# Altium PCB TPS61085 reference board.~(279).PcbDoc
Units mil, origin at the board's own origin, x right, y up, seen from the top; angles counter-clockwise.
Board outline 2400 x 2000 mil, 2 copper layers (Top Layer, Bottom Layer), stack 62 mil thick; 54 components, 22 nets, 101 pads, 29 vias.
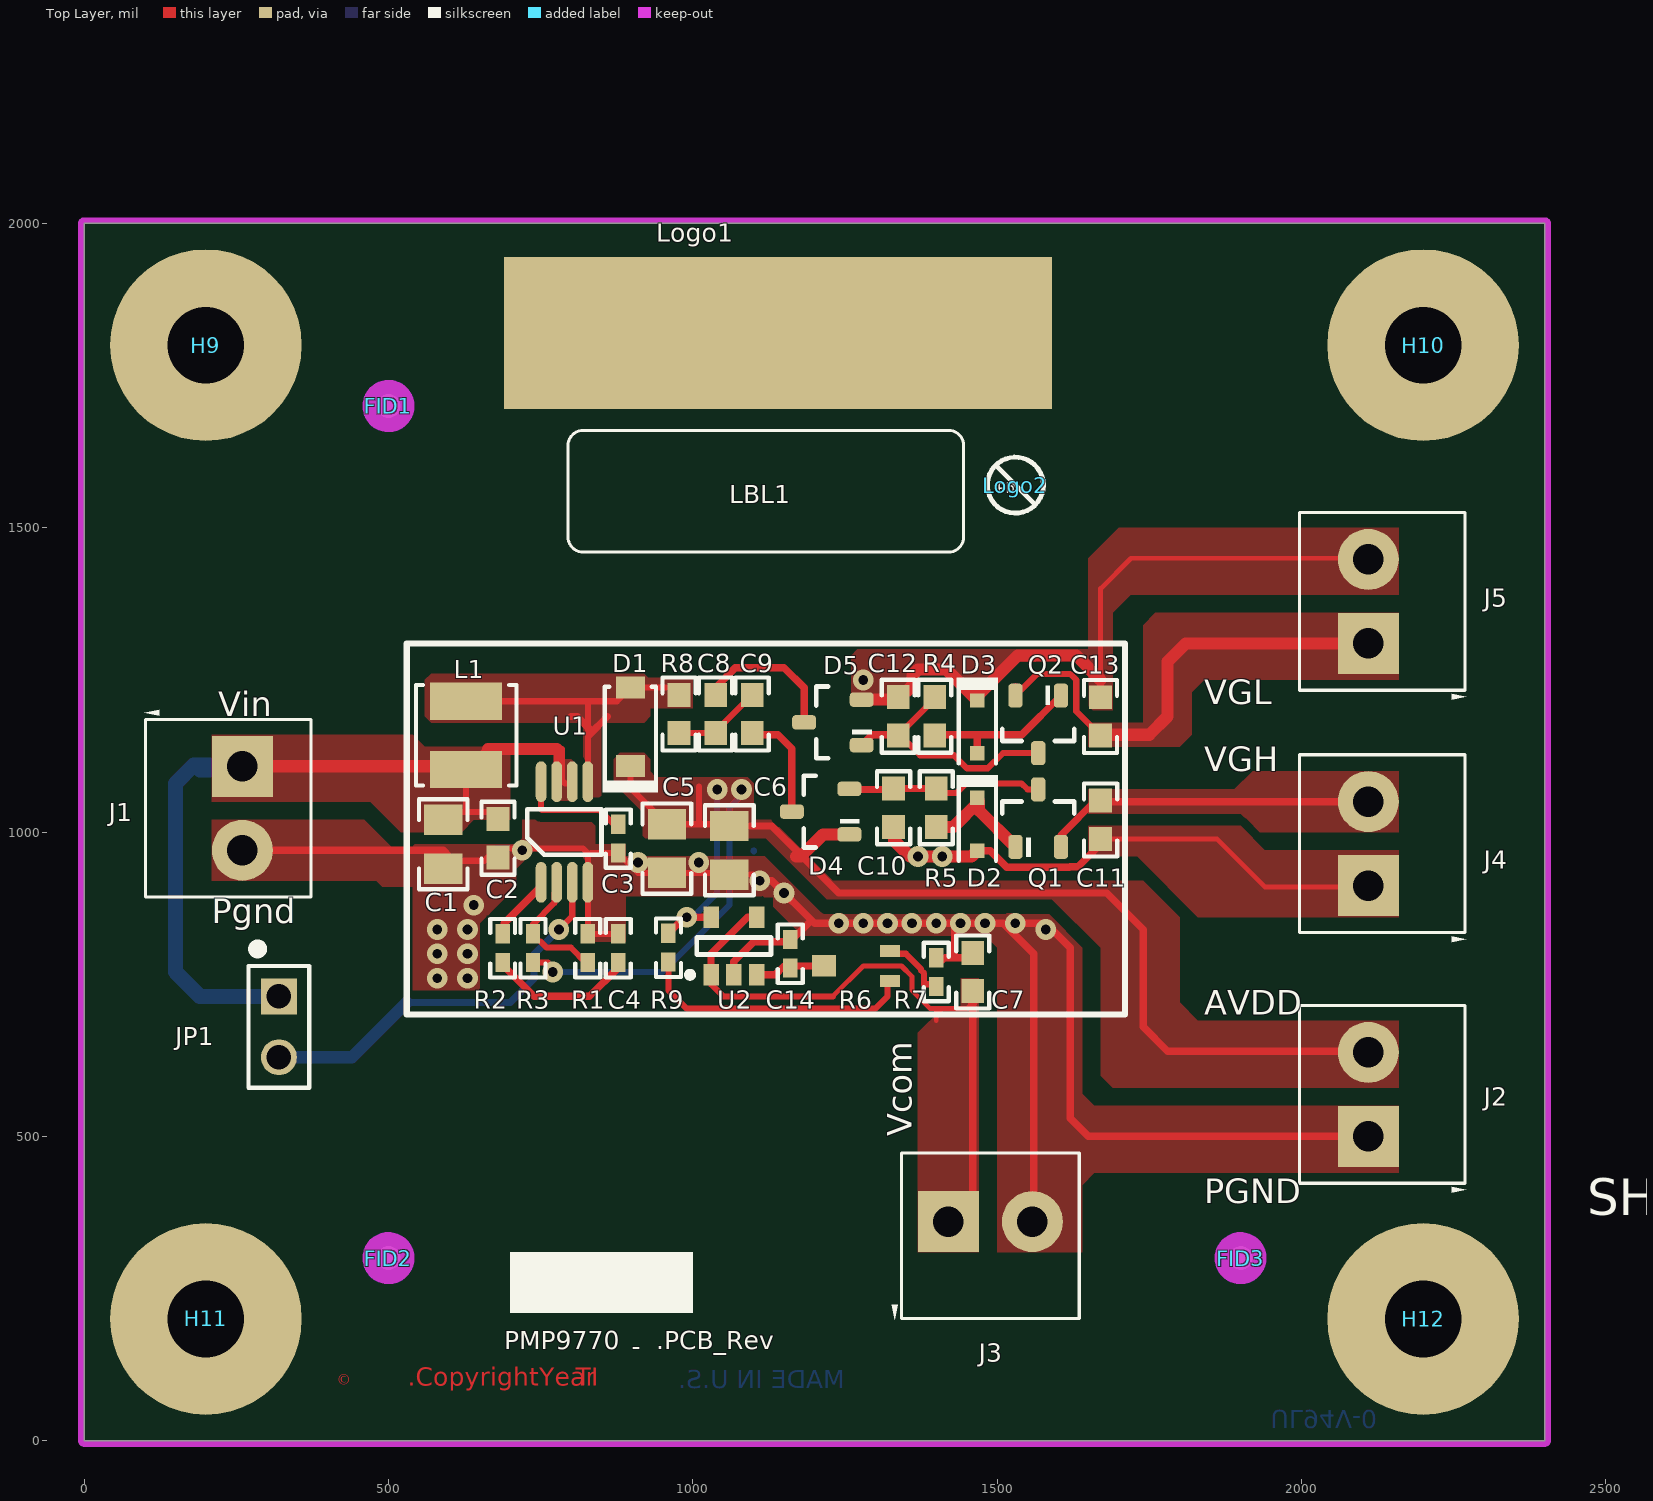
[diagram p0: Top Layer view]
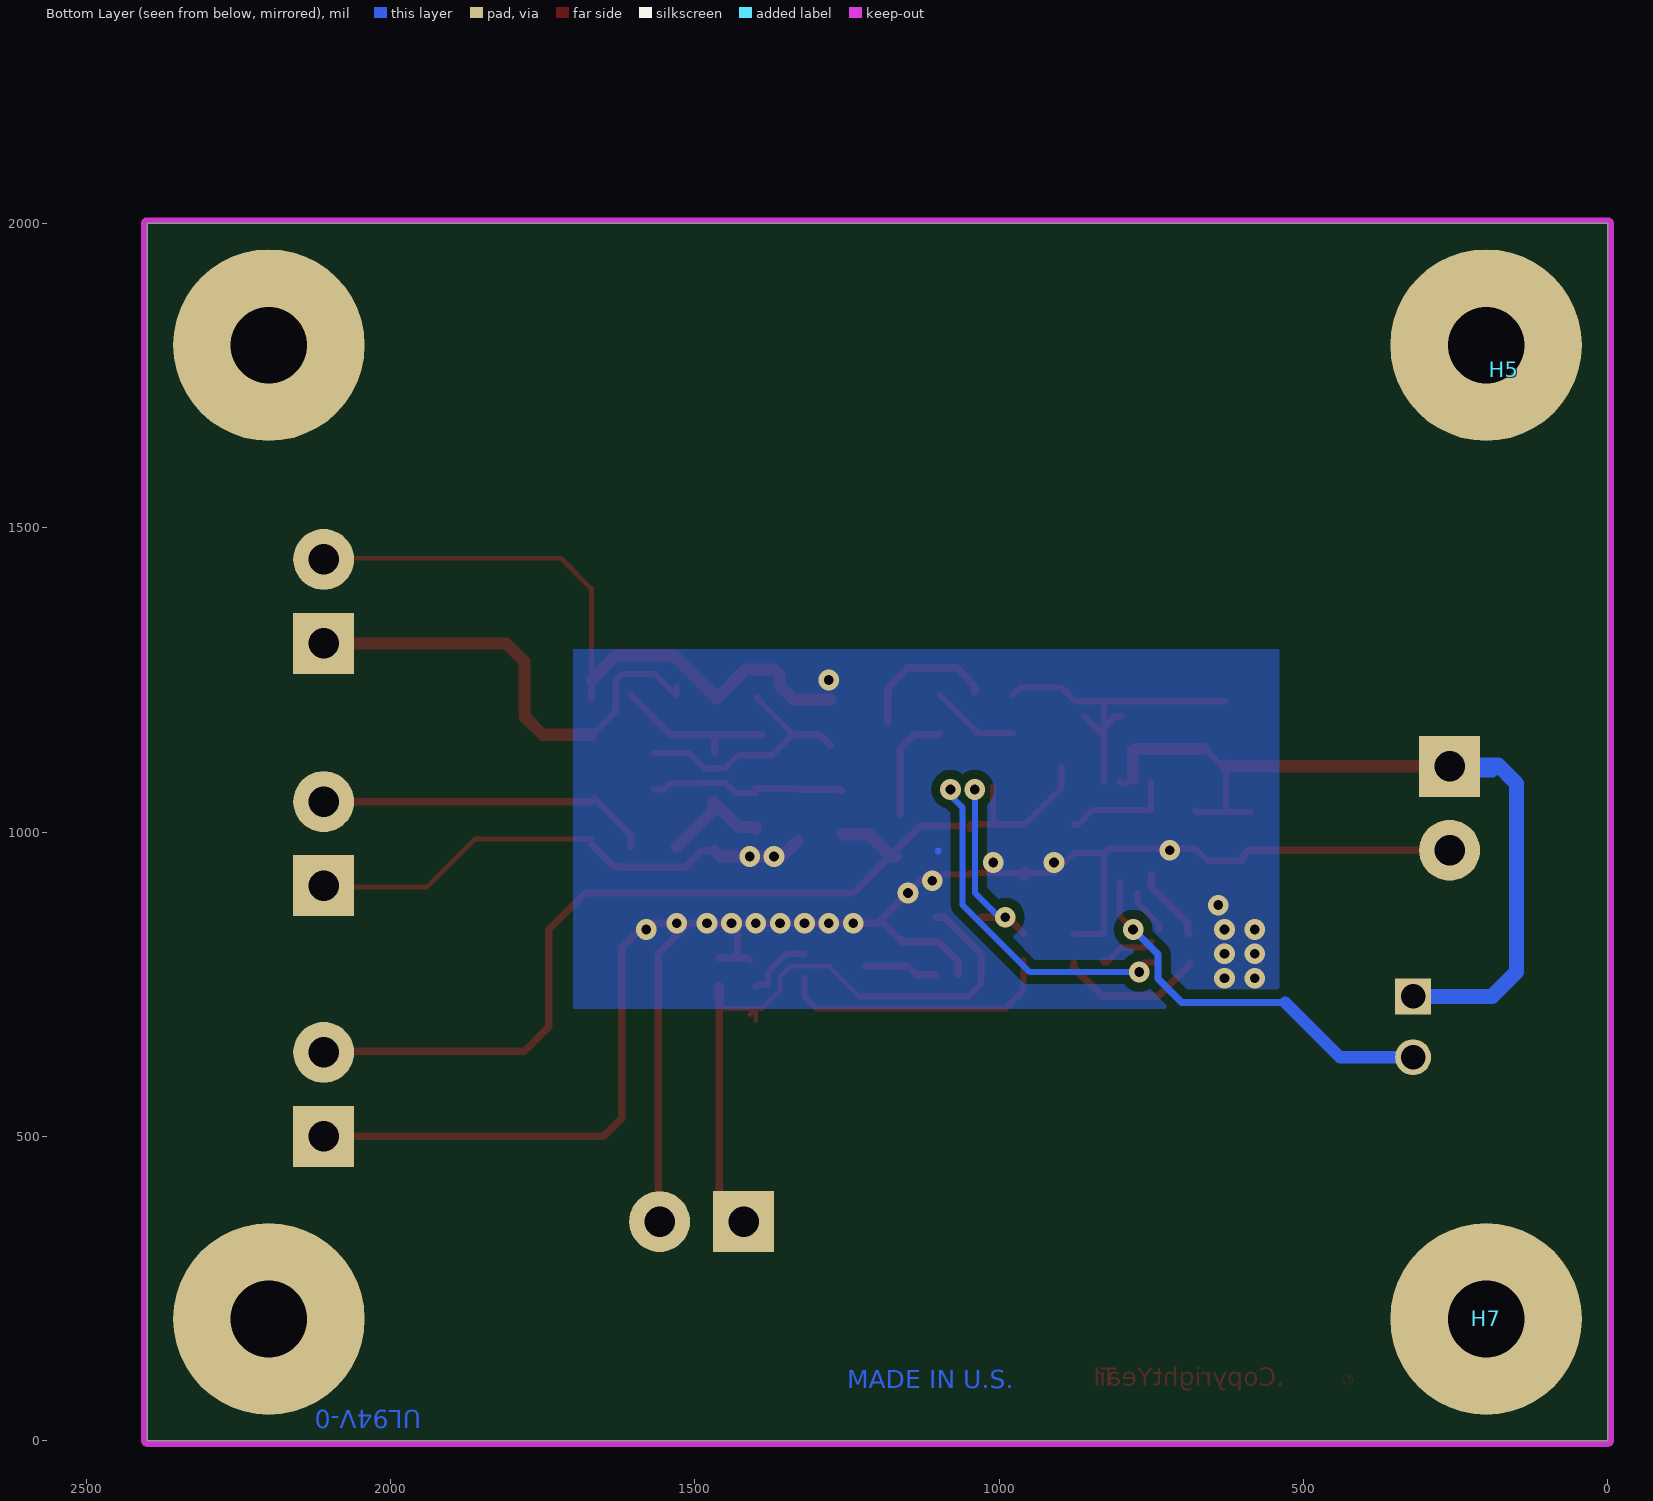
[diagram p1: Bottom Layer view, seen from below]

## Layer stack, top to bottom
Top Solder: solder mask 0.4, Solder Resist, Dk 3.5
Top Layer: signal copper 1.4
Dielectric1: core 59.2, FR-4, Dk 4.8
Bottom Layer: signal copper 1.4
Bottom Solder: solder mask 0.4, Solder Resist, Dk 3.5

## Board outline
0,0 2400,0 2400,2000 0,2000

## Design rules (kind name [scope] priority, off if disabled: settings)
AcuteAngle [All] p1: minimum=4.50000000000000E+0001 checktracksonly=FALSE
AssemblyTestPointUsage [All] p1: valid=2
Clearance Clearance_2 [InNamedPolygon('Top Layer-No Net 4')] p1: gap=10
Clearance Clearance_1 [InNamedPolygon('Top Layer-No Net 4')] p2: gap=10
Clearance Clearance_Keepouts [((IsTrack Or IsArc) And Not InPoly) And IsFree and IsKeepOut vs ((IsTrack Or IsArc) And Not InPoly) And IsFree and IsKeepOut] p3: gap=8
Clearance Clearance_BoardEdge_MountingHoles [OnCopper and InComponentClass('Mounting Holes') vs IsKeepOut] p4: gap=40
Clearance Clearance_BoardEdge_Poly [OnCopper and InPoly vs IsKeepOut] p5: gap=25
Clearance Clearance_BoardEdge [OnCopper and Not InComponentClass('Logo') and not InComponentClass('FiducialMark') and not InRegion(1000,500,4000,800) and Not IsKeepout vs IsKeepOut] p6: gap=75
Clearance Clearance_Poly [InPolygon] p7: gap=15
Clearance [All] p8: gap=7.87
ComponentClearance ComponentClearance_MountingHoles_FiducialMarks [InComponentClass('Mounting Holes') vs InComponentClass('FiducialMark')] p1: gap=10 collisioncheckmode=3 verticalgap=10 showdistances=FALSE
ComponentClearance ComponentClearance_Shunt [InComponentClass('Header') vs InComponentClass('Shunt')] p2: gap=0 collisioncheckmode=3 verticalgap=0 showdistances=FALSE
ComponentClearance ComponentClearance_Logo [InComponentClass('Logo')] p3: gap=10 collisioncheckmode=3 verticalgap=10 showdistances=FALSE
ComponentClearance ComponentClearance_ScrewToNut [(HasFootprint('NY PMS 440 0025 PH')) vs (HasFootprint('Keystone_1902C'))] p4: gap=5 collisioncheckmode=3 verticalgap=10 showdistances=FALSE
ComponentClearance ComponentClearance_MountingHoles [InComponentClass('Mounting Holes')] p5: gap=250 collisioncheckmode=3 verticalgap=100000 showdistances=FALSE
ComponentClearance ComponentClearance_SmallPassives [HasFootprint('0201*') or HasFootprint('0402*') or HasFootprint('0508') or HasFootprint('0603*') or HasFootprint('0612') or HasFootprint('0805*') or HasFootprint('0815*') or HasFootprint('0830*') or HasFootprint('1206*') or HasFootprint('1210*') or HasFootprint('1808*') or HasFootprint('1812*') or HasFootprint('1825*') or HasFootprint('2010*') or HasFootprint('2220*') or HasFootprint('2225*') or HasFootprint('2512*') or HasFootprint('2728*') or HasFootprint('3518*') vs HasFootprint('0201*') or HasFootprint('0402*') or HasFootprint('0508') or HasFootprint('0603*') or HasFootprint('0612') or HasFootprint('0805*') or HasFootprint('0815*') or HasFootprint('0830*') or HasFootprint('1206*') or HasFootprint('1210*') or HasFootprint('1808*') or HasFootprint('1812*') or HasFootprint('1825*') or HasFootprint('2010*') or HasFootprint('2220*') or HasFootprint('2225*') or HasFootprint('2512*') or HasFootprint('2728*') or HasFootprint('3518*')] p6: gap=20 collisioncheckmode=3 verticalgap=10 showdistances=FALSE
ComponentClearance ComponentClearance_THtoSMT [IsThruComponent vs IsSMTComponent] p7: gap=100 collisioncheckmode=3 verticalgap=30 showdistances=FALSE
ComponentClearance ComponentClearance_THtoTH [IsThruComponent vs IsThruComponent] p8: gap=118.11 collisioncheckmode=3 verticalgap=30 showdistances=FALSE
ComponentClearance [All] p9: gap=10 collisioncheckmode=3 verticalgap=10 showdistances=FALSE
DiffPairsRouting [All] p1: maxlimit=100 minlimit=10 mostfreqgap=10 toplayer_minwidth=15 toplayer_maxwidth=15 toplayer_prefwidth=15 bottomlayer_minwidth=15 bottomlayer_maxwidth=15 bottomlayer_prefwidth=15 maxuncoupledlength=1000
FabricationTestPointUsage TestPointUsage [All] p1: valid=2 allowmultiple=FALSE
FabricationTestpoint Testpoint [All] p1: side=3 testpointundercomponent=TRUE minsize=40 maxsize=100 preferedsize=60 minholesize=0 maxholesize=40 preferedholesize=32 testpointgrid=1 allowsidetop=TRUE allowsidebottom=TRUE usegrid=TRUE gridtolerance=0.01
FanoutControl Fanout_LCC [IsLCC] p1: bgadir=Out bgaviamode=Centered fanoutstyle=Auto fanoutdirection=Alternating viagrid=1 // Fanout_LCC (Default Rule)
FanoutControl Fanout_BGA [IsBGA] p2: bgadir=Out bgaviamode=Centered fanoutstyle=Auto fanoutdirection=Alternating viagrid=1 // Fanout_BGA (Default Rule)
FanoutControl Fanout_Default [All] p4: bgadir=Out bgaviamode=Centered fanoutstyle=Auto fanoutdirection=Alternating viagrid=1 // Fanout_Default (Default Rule)
FanoutControl Fanout_Small [(CompPinCount < 5)] p5: bgadir=Out bgaviamode=Centered fanoutstyle=Auto fanoutdirection=OutThenIn viagrid=1 // Fanout_Small (Default Rule)
HoleSize [All] p1: absolutevalues=TRUE maxlimit=251 minlimit=8 maxpercent=80.000 minpercent=20.000
MinimumAnnularRing MinimumAnnularRing_ThermalPadVias [IsVia and InAnyComponent] p1: minimumring=5.91
MinimumAnnularRing [All] p2: minimumring=9
MinimumSolderMaskSliver MinimumSolderMaskSliver_Logo [InComponentClass('Logo') vs InComponentClass('Logo')] p1: minsoldermaskwidth=0.7
MinimumSolderMaskSliver [All] p2: minsoldermaskwidth=3.94
PlaneConnect [All] p1: planeconnectstyle=Direct reliefexpansion=10 reliefentries=4 reliefconductorwidth=10 reliefairgap=10
PolygonConnect PolygonConnect_9 [All vs IsNamedPolygon('Top Layer-No Net 9')] p1: connectstyle=Direct reliefconductorwidth=10 reliefentries=4 polygonreliefangle="90 Angle" airgapwidth=10
PolygonConnect PolygonConnect_8 [All vs IsNamedPolygon('Top Layer-No Net 9')] p2: connectstyle=Direct reliefconductorwidth=10 reliefentries=4 polygonreliefangle="90 Angle" airgapwidth=10
PolygonConnect PolygonConnect_7 [All vs IsNamedPolygon('Top Layer-No Net 9')] p3: connectstyle=Direct reliefconductorwidth=10 reliefentries=4 polygonreliefangle="90 Angle" airgapwidth=10
PolygonConnect PolygonConnect_6 [All vs IsNamedPolygon('Top Layer-No Net 4')] p4: connectstyle=Direct reliefconductorwidth=10 reliefentries=4 polygonreliefangle="90 Angle" airgapwidth=10
PolygonConnect PolygonConnect_5 [All vs IsNamedPolygon('Top Layer-No Net 3') Or  IsNamedPolygon('Top Layer-No Net')] p5: connectstyle=Direct reliefconductorwidth=10 reliefentries=4 polygonreliefangle="90 Angle" airgapwidth=10
PolygonConnect PolygonConnect_4 [All vs IsNamedPolygon('Top Layer-No Net')] p6: connectstyle=Direct reliefconductorwidth=10 reliefentries=4 polygonreliefangle="90 Angle" airgapwidth=10
PolygonConnect PolygonConnect_3 [All vs IsNamedPolygon('Top Layer-No Net 2') Or  IsNamedPolygon('Top Layer-No Net')] p7: connectstyle=Direct reliefconductorwidth=10 reliefentries=4 polygonreliefangle="90 Angle" airgapwidth=10
PolygonConnect PolygonConnect_2 [All vs IsNamedPolygon('Top Layer-No Net')] p8: connectstyle=Direct reliefconductorwidth=10 reliefentries=4 polygonreliefangle="90 Angle" airgapwidth=10
PolygonConnect PolygonConnect_1 [All vs IsNamedPolygon('Top Layer-No Net')] p9: connectstyle=Direct reliefconductorwidth=10 reliefentries=4 polygonreliefangle="90 Angle" airgapwidth=10
PolygonConnect [All] p10: connectstyle=Direct reliefconductorwidth=10 reliefentries=4 polygonreliefangle="90 Angle" airgapwidth=10
RoutingVias ThermalPadVias [IsVia and InAnyComponent] p1: holewidth=7.87 width=19.68 viastyle="Through Hole" minholewidth=7.87 minwidth=19.68 maxholewidth=12.99 maxwidth=23.62
RoutingVias [All] p2: holewidth=16 width=34 viastyle="Through Hole" minholewidth=7.87 minwidth=26 maxholewidth=40 maxwidth=65
SilkToBoardRegionClearance [Not ((IsComment or IsDesignator) And (Hide <> 'False')) and not InRegion(1000,500,4000,800)] p1:
SilkToSilkClearance SilkToSilkClearance_Pb-FreeLogo [(HasFootprint('Pb-Free_Overlay_Medium') OR HasFootprint('Pb-Free_Overlay_Small')) vs (HasFootprint('Pb-Free_Overlay_Medium') OR HasFootprint('Pb-Free_Overlay_Small'))] p1: silktosilkclearance=0
SilkToSilkClearance [All] p2: silktosilkclearance=5
SilkToSolderMaskClearance "Silk to Solder Mask Opening" [All] p1: minsilkscreentomaskgap=1 clearancetoexposedcopper=FALSE
SolderMaskExpansion [All] p1: expansion=1.97
UnpouredPolygon [All] p1: allowunpoured=FALSE
Width [All] p1: maxlimit=100 minlimit=6 preferedwidth=10 checkconnectedcopper=TRUE
14 further rules are at their usual default settings.

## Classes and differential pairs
component class Shunt: SH-JP1
component class Label: LBL1
component class FiducialMark: FID1 FID2 FID3
component class "TPS61085 reference board_Hardware": FID1 FID2 FID3 H5 H6 H7 H8 H9 H10 H11 H12 LBL1 Logo1 Logo2
component class Logo: Logo1
component class "Mounting Holes": H9 H10 H11 H12
component class "TPS61085 reference board": C1 C2 C3 C4 C5 C6 C7 C8 C9 C10 C11 C12 C13 C14 D1 D2 D3 D4 D5 J1 J2 J3 J4 J5 JP1 L1 Q1 Q2 R1 R2 R3 R4 R5 R6 R7 R8 R9 SH-JP1 U1 U2

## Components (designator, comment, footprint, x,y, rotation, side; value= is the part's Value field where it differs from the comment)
C1 "GRM219R61A106KE44D" 0805_HV 590,980 r270 top
C2 "GRM185R61C105KE44D" 0603 680,990 r270 top
C3 "GRM155R71C104KA88D" 0402 877.56,989.18 r270 top
C4 "GRM155R61C222KA01D" 0402 877.56,809.18 r90 top
C5 "C2012X5R1E106K125AB" 0805_HV 957.56,972.8 r270 top
C6 "C2012X5R1E106K125AB" 0805_HV 1060,970 r270 top
C7 "GRM185R61C105KE44D" 0603 1460,770 r90 top
C8 "06035C104KAT2A" 0603 1037.56,1194 r90 top
C9 "06035C104KAT2A" 0603 1097.56,1194 r90 top
C10 "GRM188R61H105KAALD" 0603 1330,1040 r270 top
C11 "GRM188R61H105KAALD" 0603 1670,1020 r270 top
C12 "GRM185R61C105KE44D" 0603 1337.56,1190.31 r90 top
C13 "GRM185R61C105KE44D" 0603 1670,1190 r90 top
C14 "GRM155R71C104KA88D" 0402 1160,800 r90 top
D1 "MBR120LSFT1G" SOD-123FL 897.56,1172.8 r90 top
D2 "MMSZ5248BS-7-F" sod-323 1467.56,1012.8 r270 top
D3 "MMSZ5236BS-7-F" sod-323 1467.56,1172.8 r270 top
D4 "BAT54SLT1G" SOT-23 1210,1033.6 r180 top
D5 "BAT54SLT1G" SOT-23 1230.32,1180.2 r180 top
FID1 "Fiducial" Fiducial10-20 500,1700 r0 top
FID2 "Fiducial" Fiducial10-20 500,300 r0 top
FID3 "Fiducial" Fiducial10-20 1900,300 r0 top
H5 "1902C" Keystone_1902C 170,1760 r180 bottom locked
H6 "1902C" Keystone_1902C 4750,3250 r180 bottom locked
H7 "1902C" Keystone_1902C 200,200 r180 bottom locked
H8 "1902C" Keystone_1902C 4050,200 r180 bottom locked
H9 "NY PMS 440 0025 PH" "NY PMS 440 0025 PH"#1 170,1760 r0 top
H10 "NY PMS 440 0025 PH" "NY PMS 440 0025 PH"#2 2900,2200 r0 top
H11 "NY PMS 440 0025 PH" "NY PMS 440 0025 PH"#3 200,200 r0 top locked
H12 "NY PMS 440 0025 PH" "NY PMS 440 0025 PH"#4 4050,200 r0 top
J1 "ED555/2DS" TERM_BLK_ED555-2DS 260,1108 r270 top
J2 "ED555/2DS" TERM_BLK_ED555-2DS 2110,500 r90 top
J3 "ED555/2DS" TERM_BLK_ED555-2DS 1420,360 r0 top
J4 "ED555/2DS" TERM_BLK_ED555-2DS 2110,912 r90 top
J5 "ED555/2DS" TERM_BLK_ED555-2DS 2110,1310 r90 top
JP1 "PEC02SAAN" CONN_PEC02SAAN 320,680 r270 top
L1 "LQH44PN3R3MP0L" IND_LQH44P 627.56,1158.9 r90 top
LBL1 "Size: 0.65\" x 0.20 \"" Label_650x200 1120,1560 r0 top
Logo1 "Texas Instruments" TI_Stacked_SolderMask_Small 1140,1820 r180 top
Logo2 "Pb-Free Symbol" Pb-Free_Overlay_Small 1530,1570 r0 top
Q1 "BC850CLT1G" SOT-23 1567.56,1022.8 r90 top
Q2 "BC857C-7-F" SOT-23 1567.56,1177.03 r270 top
R1 "CRCW040216K0JNED" 0402 827.56,809.18 r270 top
R2 "CRCW040227K0JNED" 0402 687.56,809.18 r90 top
R3 "CRCW0402113KFKED" 0402 737.56,809.18 r270 top
R4 "CPF0603B2K0E" 0603 1397.56,1190.31 r90 top
R5 "CPF0603B2K0E" 0603 1400,1040 r90 top
R6 "3224J-1-xx" POT_2MM-SQ 1270,780 r90 top
R7 "CRCW040249K9FKED" 0402 1400,770 r90 top
R8 "CRCW060310R0FKEA" 0603 977.56,1194 r270 top
R9 "CRCW040249K9FKED" 0402 960,810 r90 top
SH-JP1 "969102-0000-DA" SNT-100-BK-G 2508,266 r90 top
U1 "TPS61085DGKR" DGK0008A_N 789.17,1000.12 r90 top
U2 "LM7321MF" MF05A_L 1067.4,812.76 r90 top

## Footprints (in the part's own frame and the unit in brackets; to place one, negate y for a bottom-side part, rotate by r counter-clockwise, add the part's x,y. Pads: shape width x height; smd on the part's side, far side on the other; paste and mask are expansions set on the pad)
0402 [mm] "0402 from SM-752 data"
  rect 0.8x0.6 smd: 1(-0.6,0) 2(0.6,0)
  silkscreen extent -1.22,-0.52 1.22,0.52, body extent -0.55,-0.3 0.55,0.3, height 0.6
0603 [mm] "0603 from SM-752 data"
  rect 1x0.95 smd: 1(-0.8,0) 2(0.8,0)
  silkscreen extent -1.52,-0.69 1.52,0.69, body extent -0.87,-0.47 0.87,0.47, height 0.85
0805_HV [mil] "0805 with 30mil clearance between pads"
  rect 50x63 smd: 1(-40,0) 2(40,0)
  silkscreen extent -74,-40 74,40, body extent -43,-29 43,29, height 43
CONN_PEC02SAAN [mm] "SULLINS"
  rect 1.5x1.5 hole 1.016: 1(-1.27,0)
  round 1.5 hole 1.016: 2(1.27,0)
  silkscreen extent -3.45,-1.27 2.54,1.27, body extent -2.54,-1.27 2.54,1.27, height 8.38
DGK0008A_N [mm] "TSOP, 8-Leads, Body 3x3mm, Pitch 0.65mm, IPC Medium Density"
  oval 1.7x0.45 smd mask+0.05: 1(-2.1,0.975) 2(-2.1,0.325) 3(-2.1,-0.325) 4(-2.1,-0.975) 5(2.1,-0.975) 6(2.1,-0.325) 7(2.1,0.325) 8(2.1,0.975)
  silkscreen extent -0.95,-1.55 0.95,1.55, body extent -2.45,-1.5 2.45,1.5, height 0.94
Fiducial10-20 [mm]
  round 1 smd mask+0.5: 1(0,0)
  Top Layer keep-out circle w1.178: c0,0 r0.5
IND_LQH44P [mm] "Murata"
  rect 1.55x3 smd: 1(-1.425,0) 2(1.425,0)
  silkscreen extent -2.1,-2.1 2.1,2.1, body extent -2.1,-2.1 2.1,2.1, height 1.8
Keystone_1902C [mil] "Hex Standoff, 4-40 threaded, nylon"
  body extent -145,-126 146,126, height 501
Label_650x200 [mil] "Thermal Transfer Label"
  silkscreen extent -325,-100 325,100, body extent -326,-101 326,101, height 1
MF05A_L [mm] "SOT23, 5-Leads, Body 2.9x1.6mm, Pitch 0.95mm, Lead Span 2.8mm, IPC High Density"
  rect 0.9x0.65 smd: 1(-1.2,0.95) 2(-1.2,0) 3(-1.2,-0.95) 4(1.2,-0.95) 5(1.2,0.95)
  silkscreen extent -1.32,-1.55 0.35,1.95, body extent -0.9,-1.55 0.9,1.55, height 1.19
"NY PMS 440 0025 PH"#1 [mm] "4-40 nylon screw and mounting hole"
  round 8 hole 3.2: 1(0.762,1.016)
  body extent -3.3,-3.3 3.3,3.3, height 2.69
"NY PMS 440 0025 PH"#2 [mm] "4-40 nylon screw and mounting hole"
  round 8 hole 3.2: 1(-17.78,-10.16)
  body extent -3.3,-3.3 3.3,3.3, height 2.69
"NY PMS 440 0025 PH"#3 [mm] "4-40 nylon screw and mounting hole"
  round 8 hole 3.2: 1(0,0)
  body extent -3.3,-3.3 3.3,3.3, height 2.69
"NY PMS 440 0025 PH"#4 [mm] "4-40 nylon screw and mounting hole"
  round 8 hole 3.2: 1(-46.99,0)
  body extent -3.3,-3.3 3.3,3.3, height 2.69
Pb-Free_Overlay_Small [mil]
  silkscreen extent -46,-46 46,46
POT_2MM-SQ [mm]
  rect 0.5x0.85 smd: 1(-0.625,-1.375) 3(0.625,-1.375)
  rect 0.9x1 smd: 2(0,1.375)
SNT-100-BK-G [mil] "Samtec STEP model"
  round 1 on Mech3: 0(0,0)
  body extent -100,-50 100,50, height 344
SOD-123FL [mm] "Copied from SOD-123"
  rect 0.915x1.22 smd: 1(-1.637,0) 2(1.637,0)
  silkscreen extent -2.74,-1.16 1.68,1.16, body extent -1.9,-0.9 1.9,0.9, height 1
sod-323 [mm] "NXP recommended land pattern"
  rect 0.6x0.6 smd paste-0.05: 1(-1.1,0) 2(1.1,0)
  silkscreen extent -2.06,-0.86 1.53,0.86, body extent -1.3,-0.67 1.3,0.68, height 1.1
SOT-23 [mm] "SOT23, 3-Leads, Body 2.9x1.3mm, Pitch 0.95mm, Lead Span 2.5mm, IPC Medium Density"
  rrect50% 1x0.6 smd: 1(-1.2,0.95) 2(-1.2,-0.95) 3(1.2,0)
  silkscreen extent -1.63,-1.5 0.7,1.5, body extent -1.16,-1.45 1.21,1.45, height 1
TERM_BLK_ED555-2DS [mil]
  rect 100x100 hole 50: 1(0,0)
  round 100 hole 50: 2(138,0)
  silkscreen extent -93,-161 215,113, body extent -69,-150 207,106, height 323
TI_Stacked_SolderMask_Small [mil]
  rect 900x250 smd paste-125 mask-125: 0(0,0)

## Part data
C1: "CAP, CERM, 10 μF, 10 V, +/- 10%, X5R, 0805"
C2 C7 C12 C13: "CAP, CERM, 1 μF, 16 V, +/- 10%, X5R, 0603"
C3 C14: "CAP, CERM, 0.1 μF, 16 V, +/- 10%, X7R, 0402"
C4: "CAP, CERM, 2200 pF, 16 V, +/- 10%, X5R, 0402"
C5 C6: "CAP, CERM, 10 μF, 25 V, +/- 10%, X5R, 0805"
C8 C9: "CAP, CERM, 0.1 μF, 50 V, +/- 10%, X7R, 0603"
C10 C11: "CAP, CERM, 1 μF, 50 V, +/- 10%, X5R, 0603"
D1: "Diode, Schottky, 20 V, 1 A, SOD-123FL"
D2: "Diode, Zener, 18 V, 200 mW, SOD-323"
D3: "Diode, Zener, 7.5 V, 200 mW, SOD-323"
D4 D5: "Diode, Schottky, 30 V, 0.2 A, SOT-23"
FID1 FID2 FID3: "Fiducial mark.  There is nothing to buy or mount."
H5 H6 H7 H8: "Standoff, Hex, 0.5\"L #4-40 Nylon"
H9 H10 H11 H12: "Machine Screw, Round, #4-40 x 1/4, Nylon, Philips panhead"
J1 J2 J3 J4 J5: "Terminal Block, 6A, 3.5mm Pitch, 2-Pos, TH"
JP1: "Header, 100mil, 2x1, Tin plated, TH"
L1: "Inductor, Shielded Drum Core, Ferrite, 3.3 μH, 1.77 A, 0.065 ohm, SMD"
LBL1: library part THT-14-423-10, "Thermal Transfer Printable Labels, 0.650\" W x 0.200\" H - 10,000 per roll"
Logo1: library part TI_Logo, "Texas Instrument Corporate Signature"
Logo2: library part Pb-Free
Q1: library part "BC850CLT1G, ON Semiconductor", "Transistor, NPN, 45 V, 0.1 A, SOT-23"
Q2: library part "BC857C-7-F, Diodes Inc.", "Transistor, PNP, 45 V, 0.1 A, SOT-23"
R1: "RES, 16 k, 5%, 0.063 W, 0402"
R2: "RES, 27 k, 5%, 0.063 W, 0402"
R3: "RES, 113 k, 1%, 0.063 W, 0402"
R4 R5: "RES, 2.00 k, 0.1%, 0.063 W, 0603"
R6: library part POT_3312_SERIES, "Potentiometer,  2 mm SMDTop-Adjust"
R7 R9: "RES, 49.9 k, 1%, 0.063 W, 0402"
R8: "RES, 10.0, 1%, 0.1 W, 0603"
SH-JP1: "Shunt, 100mil, Gold plated, Black"
U1: "18.5 V, 2 A, 650 KHz / 1.2 MHz Step-Up DC-DC Converter with Forced PWM Mode, 2.3 to 6 V, -40 to 85 degC, 8-pin SOP (DGK8), Green (RoHS & no Sb/Br)"
U2: "Single 30V High Output Current and Unlimited Capacitive Load Op Amp"

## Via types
v1: diameter 34, hole 16, Top Layer to Bottom Layer, 29 vias

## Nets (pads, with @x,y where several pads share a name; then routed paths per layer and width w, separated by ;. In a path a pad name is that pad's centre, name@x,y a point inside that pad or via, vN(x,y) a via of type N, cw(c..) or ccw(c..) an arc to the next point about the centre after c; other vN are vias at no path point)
NetC3_1: C3.1 U1.8 | length 181.8
  Top Layer w10: U1.8 750.79,1038.31 752.64,1036.46 846.28,1036.46 869.94,1012.8 C3.1
NetC4_1: C4.1 R2.1 | length 243.2
  Top Layer w10: R2.1@687.56,781.68 R2.1 ; C4.1@877.56,777.23 C4.1
  Top Layer w12: R2.1@687.56,781.68 739.23,730 830.33,730 C4.1@877.56,777.23
NetC8_1: C8.1 C9.2 R8.2 | length 147.8
  Top Layer w10: R8.2 C8.1 1037.56,1165.5 C9.2
NetC8_2: C8.2 D5.3 | length 235.9
  Top Layer w12: C8.2@1040,1230 1040,1240 1070,1270 1150,1270 1183.07,1236.93 D5.3
NetC9_1: C9.1 D4.3 | length 181.9
  Top Layer w10: C9.1 C9.1@1100,1162.5
  Top Layer w12: C9.1@1100,1160 1140,1160 1162.76,1137.24 D4.3@1162.76,1030
NetC10_1: C10.1 D4.2 Q1.3 R5.2 | length 322.2
  Top Layer w10: D4.2@1257.24,1067.4 D4.2@1260,1067.4 ; R5.2@1400,1064.29 1433.92,1064.29 1450.42,1080.79 1484.7,1080.79 1485.49,1080 1540,1080 1549.96,1070.04 Q1.3
  Top Layer w12: D4.2@1260,1070 1330,1070 1331.5,1071.5 R5.2
NetC12_1: C12.1 D5.1 Q2.3 R4.2 | length 418.5
  Top Layer w10: C12.1 1340.97,1158.82 1373.53,1126.26 1428.96,1126.26 1450.42,1104.8 1484.7,1104.8 1509.68,1129.78 Q2.3 ; C12.1@1338.74,1160 1397.56,1218.82 R4.2
  Top Layer w12: D5.1 1294.76,1160 1338.74,1160 C12.1@1340,1160
NetC14_1: C14.1 R6.2 U2.3 | length 121.2
  Top Layer w12: U2.3 1135.51,765.51 1150,780 R6.2 R6.2@1220,780
NetD2_1: D2.1 Q1.1 R5.1 | length 189
  Top Layer w10: R5.1@1397.56,1001.3 R5.1@1400,1001.3
  Top Layer w20: R5.1 1428.5,1008.5 1470,1050 1470,1035.71 Q1.1
NetD3_2: D3.2 Q2.1 R4.1 | length 273.1
  Top Layer w12: R4.1@1390,1160 1470,1160 ; D3.2 1467.56,1157.56 1470,1160 ; Q2.1 1540.69,1160 1470,1160
NetJP1_2: JP1.2 U1.3 | length 657
  Top Layer w10: v1(780,840) 801.97,861.97 U1.3
  Bottom Layer w12: 530,720 700,720 739.13,759.13 739.13,799.13 v1(780,840)
  Bottom Layer w20: JP1.2 440,630 530,720
NetR1_2: R1.2 R3.1 U1.2 | length 168.6
  Top Layer w10: R3.1@737.56,840 737.56,848.87 772.52,883.83 U1.2@772.52,900 ; 750.13,819.87 759.87,810.13 799.87,810.13 824.45,785.55 R1.2 ; R1.2@827.56,790 R1.2@830,790
NetR2_2: R2.2 U1.1 | length 123.1
  Top Layer w12: R2.2 690,835.24 690,850 750,910 U1.1@750,930
NetR6_1: R6.1 R9.1 | length 460.7
  Top Layer w10: R9.1@960,790 R9.1 960,740 990,710 1300,710 1320,730 R6.1@1320,760
NetR6_3: R6.3 R7.1 | length 113.9
  Top Layer w10: R6.3@1320,800 1350,800 1375.32,774.68 1375.32,772.54 1380,767.86 1380,750 1396.38,750 R7.1
PGND: C1.2 C2.2 C3.2 C4.2 C5.2 C6.2 C7.2 C10.2 C11.2 C12.2 C13.2 C14.2 D2.2 D3.1 D5.2 J1.2 J2.1 J3.2 J4.1 J5.2 R1.1 R7.2 U1.4 U2.2 | length 5147.7
  Top Layer w8: C11.2 1861.5,988.5 1940,910 J4.1@2110,910 ; 1670,1250 1670,1400 1720,1450 J5.2@2110,1450
  Top Layer w10: C1.2@600,952.8 657.56,952.8 677.56,972.8 819.92,972.8 827.56,965.16 827.56,960.28 ; C4.2 R1.1 U1.4 827.56,960.28 ; v1@1100,930 C6.2 1050,930 1050.18,930.18 1047.56,932.8 C5.2 910.32,932.8 C3.2 832.83,965.55 827.56,960.28
  Top Layer w12: J1.2 590,970 C1.2@600,960 ; U2.2 1067.4,787.4 1100,820 C14.2@1160,820 ; v1(1110,920) 1130,920 1200,850 v1(1400,850) v1@1430,850 ; C14.2 1163.62,823.62 1190,850 ; R7.2@1410,790 1413.62,793.62 1430,793.62 ; C7.2@1460,793.62 1430,793.62 ; D2.2 1488.56,969.49 1516.06,941.99 1619.06,941.99 1620.06,942.99 1632.99,942.99 C11.2@1670,980 ; v1(1530,850) 1580,850 1620,810 1620,530 1650,500 J2.1 ; J3.2@1560,360 1560,800 1510,850 v1(1480,850) v1(1440,850) v1@1430,850 ; C13.2@1670,1220 C13.2 1670,1250 ; 1430,793.62 v1@1430,850
  Top Layer w20: C5.2 C5.2@960,930.36 ; D5.2 1337.6,1217.6 1360.98,1240.98 1360.98,1257.92 1370,1266.93 1416.93,1266.93 1463.86,1220 1533.86,1290 1630,1290 1670,1250 ; 1330.79,985.98 1356.77,960 v1(1370,960) 1458.07,960 D2.2
  Bottom Layer w10: 1100.13,968.45 1100.13,969.87
  other v1: 580,760 630,760 580,800 630,800 580,840 630,840 1580,840 1240,850 1280,850 1320,850 1360,850 640,880 1150,900 910,950 1010,950 1410,960 720,970 1280,1250
SW: D1.2 L1.2 R8.1 U1.5 | length 588
  Top Layer w10: L1.2 830,1215 ; U1.5 827.56,1172.44 827.56,1212.56 830,1215 ; R8.1 965.79,1237.27 D1.2 875.3,1215 830,1215
  Top Layer w12: 800,1190 810,1190 827.56,1172.44 830,1170 830,1160 860,1190
VCOM: C7.1 J3.1 U2.1 U2.4 | length 1062.4
  Top Layer w8: 1230,730 1280,780 1342.89,780 1360,762.89 1360,740 1390,710 1400,710 ; 1400,690 1400,710 ; 1410,700 1400,710 ; C7.1@1458.19,748.19 C7.1@1460,750 ; C7.1@1460,720 1450,710 1400,710
  Top Layer w10: U2.1 1030,750 1050,730 1230,730
  Top Layer w12: U2.1 1030,800 1090,860 U2.4 ; J3.1@1450,380 1460,390 C7.1@1460,720
  Top Layer w15: C7.1@1460,720 C7.1@1460,746.38
VGH: C11.1 J4.2 Q1.2 | length 544.3
  Top Layer w12: Q1.2 1604.96,994.96 C11.1@1665,1055 ; C11.1@1670,1050 J4.2
VGL: C13.1 J5.1 Q2.2 | length 797.6
  Top Layer w10: Q2.2@1530.16,1240.16 Q2.2 1565.89,1260 1620,1260 1630,1250 1630,1198.5 C13.1
  Top Layer w20: C13.1@1670,1160 1750,1160 1780,1190 1780,1280 1810,1310 J5.1
VIN: C1.1 C2.1 J1.1 JP1.1 L1.1 U1.6 U1.7 | length 1500.3
  Top Layer w10: C1.1@587.56,1032.8 627.56,1032.8 ; 662.38,1137.62 L1.1 627.56,1032.8 ; C2.1@677.56,1035.79 674.57,1032.8 627.56,1032.8 ; U1.7 776.38,1136.38 ; 784.76,1136.38 784.76,1085.24 790,1080 799.17,1080 U1.6
  Top Layer w20: J1.1 628,1108 L1.1@630,1110 ; 663.62,1136.38 776.38,1136.38
  Bottom Layer w20: 190,1100 J1.1@250,1100 ; JP1.1@310,730 JP1.1
  Bottom Layer w25: J1.1 260,1110 180,1110 150,1080 150,770 190,730 JP1.1@310,730
VO: C5.1 C6.1 D1.1 D4.1 J2.2 R3.2 R9.2 U2.5 | length 2550.8
  Top Layer w10: R3.2 761.68,785.55 ; D1.1 897.56,1072.8 C5.1 1047.56,1012.8 C6.1@1047.56,1005.32 ; 1010,1020 1010,1074.76 ; v1@1047.56,1067.56 v1@1050,1070
  Top Layer w12: R9.2 986.38,860 v1(990,860) U2.5 ; C6.1 1130,1010 1178.8,961.2 1240,900 1680,900 1740,840 1740,680 1780,640 J2.2@2110,640
  Top Layer w20: 1170,960 1177.6,960 1178.8,961.2 1213.8,996.2 D4.1
  Bottom Layer w10: v1(770,770) 950,770 1060,880 1060,1040 1080,1060 v1(1080,1070) ; v1(990,860) 1000,860 1040,900 v1(1040,1070)
pads on no net: FID1.1 FID2.1 FID3.1 H9.1 H10.1 H11.1 H12.1 Logo1.0 SH-JP1.0

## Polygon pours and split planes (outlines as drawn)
VCOM on Top Layer "Top Layer-No Net 8" (solid, pour order 32): 1440,760 1440,710 1410,710 1370,670 1370,310 1470,310 1470,760
VO on Top Layer "Top Layer-No Net 1" (solid, pour order 29): 1080,1020 1130,1020 1220,930 1230,920 1650,920 1740,920 1780,880 1800,860 1800,740 1800,720 1830,690 2160,690 2160,590 2160,580 1690,580 1670,600 1670,810 1590,890 1460,890 1220,890 1120,990 1080,990 1080,1020 1100,1020
PGND on Top Layer "Top Layer-No Net" (solid, pour order 28): 1110,960 1120,960 1210,870 1580,870 1640,810 1640,570 1660,550 2160,550 2160,440 1660,440 1640,420 1640,310 1510,310 1500,310 1500,410 1500,810 1480,830 1200,830 1180,830 1090,920 1090,960 1110,960
SW on Top Layer "Top Layer-No Net 10" (solid, pour order 27): 820,1200 820,1050 840,1050 850,1050 850,1200
PGND on Top Layer "Top Layer-No Net 7" (solid, pour order 26): 880.97,960 1110,960 1123.41,939.94 1123.41,904.45 1113.58,894.45 883.41,894.45 880.97,896.89
PGND on Top Layer "Top Layer-No Net 6" (solid, pour order 25): 827.56,980 890,980 890,820 820,820 820,972.44 827.56,980
VO on Top Layer "Top Layer-No Net 5" (solid, pour order 23): 880,1130 920,1130 930,1120 930,1100 939.56,1090 1090,1090 1100,1080 1100,990 920,990 917.56,992.44 917.56,1029.8 917.56,1032.44 870,1080 870,1120
VIN on Top Layer "Top Layer-No Net 4" (solid, pour order 20): 776.38,1120 800,1120 810,1110 810,1060 800,1050 790,1050 780,1050 770,1060 770,1110 770,1113.62
SW on Top Layer "Top Layer-No Net 2" (solid, pour order 21): 560,1190 570,1180 920,1180 930,1190 930,1250 920,1260 570,1260 560,1250 560,1190
SW on Top Layer "Top Layer-No Net 3" (solid, pour order 22): 919.79,1253.8 999.79,1253.8 999.79,1203.8 919.79,1203.8 919.79,1253.8
PGND on Top Layer "Top Layer-No Net 17" (solid, pour order 30): 1660,1280 1540,1280 1530,1280 1480,1230 1450,1230 1440,1230 1410,1260 1370,1260 1370,1240 1350,1220 1260,1220 1260,1290 1270,1300 1660,1300 1660,1280
PGND on Top Layer "Top Layer-No Net 9" (solid, pour order 31): 1650,1010 1900,1010 1940,970 2160,970 2160,860 1830,860 1730,960 1650,960 1650,1010
VGH on Top Layer "Top Layer-No Net 11" (solid, pour order 33): 1650,1070 1890,1070 1920,1100 2160,1100 2160,1000 1940,1000 1930,1000 1900,1030 1650,1030 1650,1070
PGND on Top Layer "Top Layer-No Net 12" (solid, pour order 34): 2160,1500 1700,1500 1650,1450 1650,1200 1690,1200 1690,1360 1720,1390 2160,1390
VGL on Top Layer "Top Layer-No Net 13" (solid, pour order 35): 2160,1360 1760,1360 1740,1340 1740,1180 1650,1180 1650,1140 1770,1140 1800,1140 1820,1160 1820,1230 1840,1250 2160,1250 2160,1360
VIN on Top Layer "Top Layer-No Net 14" (solid, pour order 36): 210,1160 510,1160 540,1160 560,1140 700,1140 700,1020 640,1020 620,1000 540,1000 520,1000 470,1050 210,1050 210,1160
PGND on Top Layer "Top Layer-No Net 15" (solid, pour order 37): 210,1020 460,1020 510,970 660,970 660,980 700,980 700,910 490,910 480,920 210,920 210,1020
PGND on Top Layer "Top Layer-No Net 16" (solid, pour order 38): 690,980 710,980 720,990 720,1020 830,1020 840,1010 840,980 890,980 890,970 740,970 710,940 710,920 710,910 670,870 650,850 650,740 540,740 540,980
PGND on Bottom Layer "Bottom Layer-No Net" (solid, pour order 24): 540,1300 1700,1300 1700,710 540,710

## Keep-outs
Keep-Out Layer:
  lines w10: -5,0 ccw(c0,0) 0,-5 ; -5,0 ccw(c0,0) 0,-5 ; -5,0 -5,2000 ; -5,2000 cw(c0,2000) 0,2005 ; -5,2000 cw(c0,2000) 0,2005 ; 0,-5 2400,-5 ; 0,2005 2400,2005 ; 2400,-5 ccw(c2400,0) 2405,0 ; 2400,-5 ccw(c2400,0) 2405,0 ; 2400,2005 cw(c2400,2000) 2405,2000 ; 2400,2005 cw(c2400,2000) 2405,2000 ; 2405,0 2405,2000
  text ".Layer_Name" at 577,-858.49 h30

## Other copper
Top Layer:
  text ".CopyrightYear" at 532,90 h30
  text "TI" at 808,90 h30
  text "©" at 415,86.48 h30
  text ".Layer_Name" at 577,-858.49 h30
Bottom Layer:
  text ".VersionControl_RevNumber" at 3891,179.5 h30
  text "SVN:" at 4130,180 h30
  text "MADE IN U.S." at 1250,86.5 h30
  text "UL94V-0" at 1950,50 h30 r180
  text ".Layer_Name" at 577,-858.49 h30

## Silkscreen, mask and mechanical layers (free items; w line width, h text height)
Top Overlay:
  region: 1000,310 700,310 700,210 1000,210
  lines w10: 530,700 530,1310 1710,1310 1710,700 530,700
  text "VGL" at 1840,1210 h40
  text "Vin" at 220,1190 h40
  text "VGH" at 1840,1100 h40
  text "Pgnd" at 210,850 h40
  text "AVDD" at 1840,700 h40
  text "Vcom" at 1360,500 h40 r90
  text "PGND" at 1840,390 h40
  text "PMP9770" at 690,150 h30
  text ".PCB_Rev" at 940,150 h30
  text "-" at 900,140 h30
  text ".Layer_Name" at 577,-858.49 h30
Bottom Overlay:
  text ".Layer_Name" at 577,-858.49 h30
Top Paste:
  text ".Layer_Name" at 577,-858.49 h30
Bottom Paste:
  text ".Layer_Name" at 577,-858.49 h30
Top Solder:
  text ".Layer_Name" at 577,-858.49 h30
  text ".Layer_Name" at 577,-858.49 h30
Bottom Solder:
  text ".Layer_Name" at 577,-858.49 h30
Drill Guide:
  text ".Layer_Name" at 577,-858.49 h30
M1 Board Outline:
  lines w10: 690,-1530 700,-1530 ; 0,0 0,2000 2400,2000 2400,0 0,0
  text ".Layer_Name" at 577,-858.49 h30
M2 Board Dimensions:
  rectangle: 125,-400 500,-275
  rectangle: 0,-275 125,-150
  lines w7: 0,-275 1000,-275 ; 125,-400 125,-150 ; 250,-400 250,-150 ; 500,-400 500,-150 ; 750,-400 750,-150 ; 0,-400 0,-150 1000,-150 1000,-400 0,-400
  text ".Layer_Name" at 577,-858.49 h30
M3 3D STEP Top:
  text ".Layer_Name" at 577,-858.49 h30
M4 3D STEP Bottom:
  text ".Layer_Name" at 577,-858.49 h30
M5 Assembly Top:
  lines w10: -292,-930.17 6308,-930.17 ; -292,-726.83 6310,-726.83 ; -292,-523.5 -292,-1133.5 3713,-1133.5 6310,-1133.5 6310,-523.5 -291.5,-523.5 -291.5,-1133.5 1284,-1133.5 ; 2173,-1133.5 2173,-523.5 ; 3440,-726.83 3440,-523.5 ; 4280,-726.83 4280,-523.5 ; 4902,-1140 4902,-937.17
  text "COMPONENTS MARKED 'DNP' SHOULD NOT BE POPULATED." at 1153.5,-318.5 h30
  text "ASSEMBLY VARIANT:" at 1153,-434 h30
  text ".VariantName" at 2189,-434 h30
  text "PCB VIEWED FROM TOP SIDE" at -228.5,-655.67 h30
  text "BOARD #:" at 2248,-655.67 h30
  text ".PRJ_Number" at 2793.5,-655.67 h30
  text "REV:" at 3638,-655.67 h30
  text ".PCB_Rev" at 3929.5,-655.67 h30
  text "SVN REV:" at 4476,-655.67 h30
  text ".VersionControl_RevNumber" at 4982,-655.67 h30
  text "PLOT NAME =" at -228.5,-1064.34 h30
  text ".plot_File_Name" at 577,-1064.34 h30
  text "GENERATED    :" at 2250,-1064.34 h30
  text ".Print_Date" at 3119.5,-1064.34 h30
  text ".Print_Time" at 3848.5,-1064.34 h30
  text "TEXAS INSTRUMENTS" at 5113,-1064.34 h30
M6 Assembly Bottom:
  lines w10: -292.5,-727.33 6309.5,-727.33 ; -290.5,-930.67 6309.5,-930.67 ; 1115.5,-1140.5 1115.5,-937.67 ; 1737.5,-727.33 1737.5,-524 ; 2577.5,-727.33 2577.5,-524 ; 3844.5,-1134 3844.5,-524 ; 4733.5,-1134 6309,-1134 6309,-524 -292.5,-524 -292.5,-1134 2304.5,-1134 6309.5,-1134 6309.5,-524
  text "COMPONENTS MARKED 'DNP' SHOULD NOT BE POPULATED." at 6102,-318 h30
  text ".VariantName" at 5058,-434 h30
  text "ASSEMBLY VARIANT:" at 6097,-434 h30
  text ".VersionControl_RevNumber" at 1035.5,-656.17 h30
  text "SVN REV:" at 1541.5,-656.17 h30
  text ".PCB_Rev" at 2088,-656.17 h30
  text "REV:" at 2379.5,-656.17 h30
  text ".PRJ_Number" at 3224,-656.17 h30
  text "BOARD #:" at 3769.5,-656.17 h30
  text "PCB VIEWED FROM BOTTOM SIDE" at 6246,-656.17 h30
  text "TEXAS INSTRUMENTS" at 904.5,-1064.84 h30
  text ".Print_Time" at 2169,-1064.84 h30
  text ".Print_Date" at 2898,-1064.84 h30
  text "GENERATED    :" at 3767.5,-1064.84 h30
  text ".plot_File_Name" at 5440.5,-1064.84 h30
  text "PLOT NAME =" at 6246,-1064.84 h30
M9 Title Sheet:
  drawing of 57 lines, arcs and shapes, not listed
  text "1" at 739.84,8036.5 h30
  text "2" at 3235.5,8036.5 h30
  text "3" at 5724.84,8036.5 h30
  text "4" at 8231.51,8036.5 h30
  text "5" at 10730.5,8036.5 h30
  text "6" at 13235.5,8036.5 h30
  text "A" at -416.5,6893.5 h30
  text "A" at 14383.5,6893.5 h30
  text "B" at -416.5,4513.5 h30
  text "B" at 14383.5,4513.5 h30
  text "C" at -416.5,2138.5 h30
  text "C" at 14383.5,2138.5 h30
  text "PROJECT TITLE:" at 11343.5,277.5 h30
  text ".PRJ_Title" at 11393.5,144.17 h30
  text "DESIGNED FOR:" at 11343.5,-23.5 h30
  text ".PRJ_Customer" at 11393.5,-163.5 h30
  text "D" at -416.5,-231.5 h30
  text "D" at 14383.5,-231.5 h30
  text "FILE NAME:" at 11343.5,-323.5 h30
  text ".PCB_File_Name_No_Path" at 11393.5,-443.5 h30
  text "Texas Instruments (TI) and/or its licensors do not warrant the accuracy or completeness of this specification" at 6374,-605.34 h30
  text "ENGINEER:" at 11343.5,-613.5 h30
  text "LAYOUT BY:" at 12848.5,-613.5 h30
  text "or any information contained therein. TI and/or its licensors do not warrant that this design will meet" at 6329.01,-718 h30
  text ".PRJ_Engineer" at 11393.5,-768.49 h30
  text ".PCB_Layout" at 12899,-768.49 h30
  text "the specifications, will be suitable for your application or fit for any particular purpose, or will operate in" at 6329.01,-830.67 h30
  text ".Layer_Name" at 577,-858.49 h30
  text "ALTIUM DESIGNER VERSION:" at 12848.5,-923.5 h30
  text "an implementation. TI and/or its licensors do not warrant that the design is production worthy. You should" at 6329.01,-943.33 h30
  text "completely validate and test your design implementation to confirm the system functionality for your application." at 6374,-1056 h30
  text ".print_Scale" at 11393.5,-1056.83 h30
  text ".Application_BuildNumber" at 12899,-1056.83 h30
  text "1" at 739.84,-1263.5 h30
  text "2" at 3235.5,-1263.5 h30
  text "3" at 5724.84,-1263.5 h30
  text "4" at 8231.51,-1263.5 h30
  text "5" at 10730.5,-1263.5 h30
  text "6" at 13235.5,-1263.5 h30
M10 Fab Notes:
  drawing of 185 lines, arcs and shapes, not listed
  text "DESIGN INFORMATION" at 12381.02,5910 h30
  text "MIN. TRACK WIDTH:" at 11736.46,5730 h30
  text "8" at 12832.7,5730 h30
  text "MIL" at 12987.46,5730 h30
  text "MIN. CLEARANCE:" at 11736.46,5598 h30
  text "0.2" at 12772.7,5598 h30
  text "mm" at 12987.46,5598 h30
  text "MIN. VIA PAD SIZE:" at 11736.46,5466 h30
  text "24" at 12802.71,5466 h30
  text "MIL" at 12987.46,5466 h30
  text "0.05mm (2MIL)" at 12431.46,5324.29 h30
  text "MINIMUM ANNULAR RING" at 11407.23,5320 h30
  text "EXTERNAL" at 13139.46,5320 h30
  text "PER" at 11607.23,5202 h30
  text "IPC-D-275 CLASS 2 LEVEL C" at 11827.23,5202 h30
  text "MIL, HOLES" at 13315.46,5089.71 h30
  text "+/-" at 12923,5089 h30
  text "+/-" at 13777,5089 h30
  text "REGISTRATION TOLERANCES:" at 11407.23,5084 h30
  text "METAL" at 12607,5084 h30
  text "5" at 13183.2,5084 h30
  text "3" at 14016.2,5084 h30
  text "MIL" at 14132.46,5084 h30
  text "MATERIAL:" at 11332.46,4874.54 h30
  text "FR-4 High Tg" at 12318.9,4734.21 h30
  text "FR-408" at 11753.46,4725.64 h30
  text "X" at 12165.46,4725.64 h30
  text "OTHER" at 13241.46,4725.64 h30
  text "62 MIL (1.6mm) +/-10%" at 12073.56,4562.92 h30
  text "THICKNESS:" at 11407.23,4558.64 h30
  text "X" at 11945.4,4558.64 h30
  text "OTHER" at 13358.46,4558.64 h30
  text "TOLERANCE:" at 11407.23,4400.64 h30
  text "X" at 12246.53,4400.64 h30
  text "ANSI IPC-6012 TYPE 3 CLASS 2" at 12433.48,4400.64 h30
  text "OTHER +/-" at 12433.46,4244.64 h30
  text "BOW & TWIST:" at 11407.23,4087.64 h30
  text "X" at 12246.53,4087.64 h30
  text "ANSI IPC-6012 TYPE 3 CLASS 2" at 12433.48,4087.64 h30
  text "OTHER +/-" at 12433.46,3929.13 h30
  text "DRILLING:" at 11332.46,3790.64 h30
  text "REFERENCE:" at 11407.23,3673.64 h30
  text "X" at 12055.46,3673.64 h30
  text "AS SHOWN" at 12242.46,3673.64 h30
  text "X" at 12956.46,3673.64 h30
  text "NC_DRILL FILES" at 13093.46,3673.64 h30
  text "PTH MIN COPPER THICKNESS:" at 11407.23,3515.64 h30
  text "X" at 12757.46,3515.64 h30
  text "1MIL" at 12894.46,3515.64 h30
  text "OTHER" at 13391.46,3515.64 h30
  text "BOARD FINISH:" at 11332.46,3356.64 h30
  text "SILKSCREEN:" at 11487.68,3238.64 h30
  text "X" at 12436.46,3238.64 h30
  text "TOP" at 12562.46,3238.64 h30
  text "X" at 12946.46,3238.64 h30
  text "BOTTOM" at 13073.46,3238.64 h30
  text "SILKSCREEN COLOR:" at 11487.68,3071.64 h30
  text "X" at 12435.42,3071.64 h30
  text "WHITE" at 12562.46,3071.64 h30
  text "OTHER" at 13073.46,3071.64 h30
  text "SOLDER RESIST COLOR:" at 11487.68,2901.64 h30
  text "X" at 12055.42,2742.44 h30
  text "GREEN" at 12182.46,2742.44 h30
  text "BLUE" at 12773.46,2742.44 h30
  text "OTHER" at 13311.46,2742.44 h30
  text "IMMERSION GOLD (ENIG)" at 12393.46,2553.92 h30
  text "ENEPIG" at 13731,2550.64 h30
  text "SURFACE FINISH:" at 11332.46,2549.64 h30
  text "X" at 12206.51,2549.64 h30
  text "IMM. TIN/SILVER OR EQUIV" at 11662,2392.64 h30
  text "OTHER" at 13093.46,2392.64 h30
  text "ARRAY/PANEL:" at 11332.46,2213.64 h30
  text "CUT AND TRIM PER MECH LAYER 1" at 12393.46,2209.35 h30
  text "N.C. ROUTE" at 12393.46,2057.64 h30
  text "X" at 13072.46,2057.64 h30
  text "V. SCORE" at 13259.46,2057.64 h30
  text "CERTIFICATION:" at 11332.46,1920.64 h30
  text "MATERIALS AND WORKMANSHIP FOR ALL PCBS" at 12057.46,1920.64 h30
  text "TO MEET OR EXCEED THE REQUIREMENTS OF:" at 12057.46,1822.64 h30
  text "X" at 11683.96,1686.13 h30
  text "ANSI IPC-A-600F CLASS ->" at 11822.96,1686.13 h30
  text "X" at 13462.02,1686.13 h30
  text "2" at 13580.96,1686.14 h30
  text "1" at 13265.96,1684.64 h30
  text "3" at 13934.96,1684.64 h30
  text "X" at 11686.02,1526.64 h30
  text "UL 94V-0" at 11822.96,1526.64 h30
  text "X" at 12498.02,1526.64 h30
  text "RoHS" at 12634.96,1526.64 h30
  text "OTHER" at 13279.36,1526.64 h30
  text "PER ORDER" at 13676.42,1526.64 h30
  text "ADDITIONAL REQUIREMENTS:" at 11332.46,1385.64 h30
  text "MICROSECTION:" at 11407.23,1270.64 h30
  text "YES" at 12312.96,1270.64 h30
  text "REQUIRED" at 13174.46,1114.49 h30
  text "BARE BOARD ELEC. TEST:" at 11407.23,1111.64 h30
  text "NONE" at 12712.96,1111.64 h30
  text "X" at 13047.46,1111.64 h30
  text "PER ORDER" at 13766.46,1111.64 h30
  text "MANUFACTURER'S UL:" at 11407.23,954.64 h30
  text "RAIL" at 12572.96,950.35 h30
  text "METAL" at 13064.77,950.35 h30
  text "X" at 13440,950 h30
  text "SILK" at 13576.46,950.35 h30
  text ".Layer_Name" at 577,-858.49 h30
M11 Gerber Information:
  lines w10: -292,-930.17 6308,-930.17 ; -292,-726.83 6310,-726.83 ; -292,-523.5 -292,-1133.5 3713,-1133.5 6310,-1133.5 6310,-523.5 -291.5,-523.5 -291.5,-1133.5 1284,-1133.5 ; 2173,-1133.5 2173,-523.5 ; 3440,-726.83 3440,-523.5 ; 4280,-726.83 4280,-523.5 ; 4902,-1140 4902,-937.17
  text "ALL ARTWORK VIEWED FROM TOP SIDE" at -228.5,-655.67 h30
  text "BOARD #:" at 2248,-655.67 h30
  text ".PRJ_Number" at 2793.5,-655.67 h30
  text "REV:" at 3638,-655.67 h30
  text ".PCB_Rev" at 3929.5,-655.67 h30
  text "SVN REV:" at 4476,-655.67 h30
  text ".VersionControl_RevNumber" at 4982,-655.67 h30
  text "LAYER NAME =" at -228.5,-858.49 h30
  text "PLOT NAME =" at -228.5,-1064.34 h30
  text ".plot_File_Name" at 577,-1064.34 h30
  text "GENERATED    :" at 2250,-1064.34 h30
  text ".Print_Date" at 3119.5,-1064.34 h30
  text ".Print_Time" at 3848.5,-1064.34 h30
  text "TEXAS INSTRUMENTS" at 5113,-1064.34 h30
M12 Stackup:
  drawing of 191 lines, arcs and shapes, not listed
  text "Layer" at 9760.34,7380 h30
  text "Name" at 9965.3,7380 h30
  text "Material" at 10430.17,7380 h30
  text "Thickness" at 10860.06,7380 h30
  text "Constant" at 11184.97,7380 h30
  text "Board Layer Stack" at 11469.9,7380 h30
  text "1" at 9760.34,7320 h30
  text "Top Overlay" at 9965.3,7320 h30
  text "2" at 9760.34,7260 h30
  text "Top Solder" at 9965.3,7260 h30
  text "Solder Resist" at 10430.17,7260 h30
  text "0.40mil" at 10860.06,7260 h30
  text "3.5" at 11184.97,7260 h30
  text "3" at 9760.34,7200 h30
  text "Top Layer" at 9965.3,7200 h30
  text "Copper" at 10430.17,7200 h30
  text "1.40mil" at 10860.06,7200 h30
  text "4" at 9760.34,7140 h30
  text "Dielectric1" at 9965.3,7140 h30
  text "FR-4" at 10430.17,7140 h30
  text "59.20mil" at 10860.06,7140 h30
  text "4.8" at 11184.97,7140 h30
  text "5" at 9760.34,7080 h30
  text "Bottom Layer" at 9965.3,7080 h30
  text "Copper" at 10430.17,7080 h30
  text "1.40mil" at 10860.06,7080 h30
  text "6" at 9760.34,7020 h30
  text "Bottom Solder" at 9965.3,7020 h30
  text "Solder Resist" at 10430.17,7020 h30
  text "0.40mil" at 10860.06,7020 h30
  text "3.5" at 11184.97,7020 h30
  text "7" at 9760.34,6960 h30
  text "Bottom Overlay" at 9965.3,6960 h30
  text ".Layer_Name" at 577,-858.49 h30
M13 Component Bodies Top:
  text ".Layer_Name" at 577,-858.49 h30
M14 Component Bodies Bottom:
  text ".Layer_Name" at 577,-858.49 h30
M15 Courtyards Top:
  text ".Layer_Name" at 577,-858.49 h30
M16 Courtyards Bottom:
  text ".Layer_Name" at 577,-858.49 h30
Drill Drawing:
  circle w1: c5653.79,3142.43 r14.51
  lines w1: 5639.28,3040.87 5668.3,3040.87 5668.3,3069.89 5639.28,3069.89 5639.28,3040.87 ; 5639.28,3222.22 5646.54,3222.22 5653.79,3214.97 5661.05,3222.22 5668.3,3222.22 5661.05,3229.48 5668.3,3236.73 5661.05,3236.73 5653.79,3243.99 5646.54,3236.73 5639.28,3236.73 5646.54,3229.48 5639.28,3222.22 ; 5639.28,3331.03 5668.3,3331.03 5653.79,3302.02 5639.28,3331.03
  lines w12: 5600,3014.76 6728.61,3014.76 ; 5600,3362.95 6728.61,3362.95 ; 5801.33,2927.71 5801.33,3450 ; 5992.26,2927.71 5992.26,3450 ; 6335.48,2927.71 6335.48,3450 ; 6489.98,2927.71 6489.98,3450 ; 5600,2927.71 6728.61,2927.71 6728.61,3450 5600,3450 5600,2927.71
  text "Symbol" at 5652.23,3389.07 h36
  text "Quantity" at 5827.44,3389.07 h36
  text "Finished Hole Size" at 6018.38,3389.07 h36
  text "Plated" at 6361.59,3389.07 h36
  text "Hole Type" at 6516.1,3389.07 h36
  text "29" at 5827.44,3302.02 h30
  text "16.00mil (0.406mm)" at 6018.38,3302.02 h30
  text "PTH" at 6361.59,3302.02 h30
  text "Round" at 6516.1,3302.02 h30
  text "2" at 5827.44,3214.97 h30
  text "40.00mil (1.016mm)" at 6018.38,3214.97 h30
  text "PTH" at 6361.59,3214.97 h30
  text "Round" at 6516.1,3214.97 h30
  text "10" at 5827.44,3127.92 h30
  text "50.00mil (1.270mm)" at 6018.38,3127.92 h30
  text "PTH" at 6361.59,3127.92 h30
  text "Round" at 6516.1,3127.92 h30
  text "4" at 5827.44,3040.87 h30
  text "125.98mil (3.200mm)" at 6018.38,3040.87 h30
  text "PTH" at 6361.59,3040.87 h30
  text "Round" at 6516.1,3040.87 h30
  text "45 Total" at 5827.44,2953.83 h30
  text ".Layer_Name" at 577,-858.49 h30

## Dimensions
0,0 to 2400,0 on M2 Board Dimensions
0,0 to 0,2000 on M2 Board Dimensions
0,-400 to 1000,-400 on M2 Board Dimensions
